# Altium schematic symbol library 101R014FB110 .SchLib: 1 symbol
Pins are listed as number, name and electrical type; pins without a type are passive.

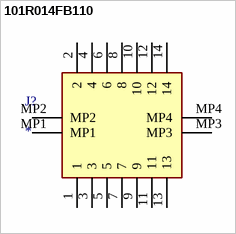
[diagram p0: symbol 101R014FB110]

## 101R014FB110
designator J?
14pin + 2 power paths, 0.35mm pitch; Manufacturer_Name: Amphenol ICC / Aorora; Manufacturer_Part_Number: 101R014FB110
footprint 101R014FB110
pins: 1, 2, 3, 4, 5, 6, 7, 8, 9, 10, 11, 12, 13, 14, MP1, MP2, MP3, MP4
